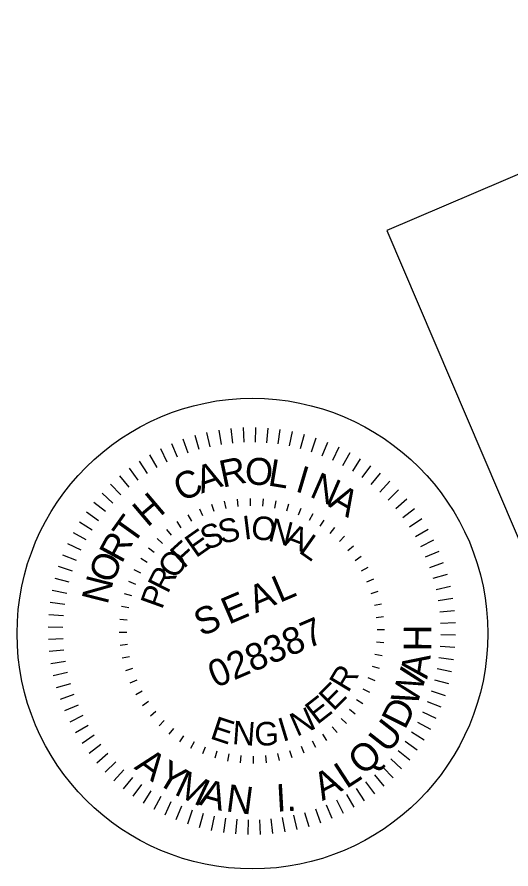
# Model space of a CAD drawing. Extents: x 1882804 to 2194450, y 87424 to 845437.
# Drawn here: x 2194046.1 to 2194137, y 87423.9 to 87580.8 of the extents above; entities that cross this region are included whole.
import ezdxf

# ---------------------------------------------------------------- set-up
doc = ezdxf.new("R2010")
doc.units = 0
doc.layers.add('Scratch_Level_1', color=7, linetype='Continuous')
doc.layers.add('Sheet Title CELL', color=7, linetype='Continuous')

msp = doc.modelspace()

# ---------------------------------------------------------------- linework, layer by layer
at = {"layer": 'Scratch_Level_1'}
msp.add_lwpolyline([(2194158.31, 87438.05), (2194250.33, 87477.33), (2194206.15, 87580.8), (2194114.14, 87541.51)], close=True, dxfattribs=at)
msp.add_circle((2194089.41, 87467.25), 43.34, dxfattribs=at)
msp.add_circle((2194089.41, 87467.25), 43.34, dxfattribs=at)
at = {"layer": 'Sheet Title CELL'}
for p, q in [((2194081.63, 87501.66), (2194081.03, 87504.31)), ((2194083.69, 87502.06), (2194083.26, 87504.74)), ((2194085.77, 87502.34), (2194085.5, 87505.04)), ((2194087.87, 87502.49), (2194087.76, 87505.2)), ((2194089.97, 87502.51), (2194090.02, 87505.22)), ((2194092.07, 87502.41), (2194092.29, 87505.11)), ((2194094.16, 87502.18), (2194094.54, 87504.86)), ((2194096.23, 87501.82), (2194096.77, 87504.48)), ((2194077.59, 87500.49), (2194076.68, 87503.04)), ((2194079.59, 87501.14), (2194078.84, 87503.74)), ((2194098.28, 87501.34), (2194098.98, 87503.96)), ((2194100.29, 87500.74), (2194101.15, 87503.31)), ((2194073.73, 87498.84), (2194072.52, 87501.27)), ((2194075.64, 87499.72), (2194074.57, 87502.22)), ((2194102.26, 87500.01), (2194103.27, 87502.53)), ((2194104.19, 87499.17), (2194105.35, 87501.62)), ((2194071.88, 87497.85), (2194070.52, 87500.19)), ((2194106.06, 87498.21), (2194107.37, 87500.59)), ((2194107.87, 87497.15), (2194109.32, 87499.44)), ((2194070.09, 87496.74), (2194068.6, 87499)), ((2194109.61, 87495.97), (2194111.19, 87498.17)), ((2194066.74, 87494.21), (2194064.98, 87496.28)), ((2194068.38, 87495.53), (2194066.75, 87497.69)), ((2194111.28, 87494.7), (2194112.99, 87496.8)), ((2194065.18, 87492.8), (2194063.3, 87494.76)), ((2194112.87, 87493.32), (2194114.7, 87495.31)), ((2194063.71, 87491.3), (2194061.72, 87493.14)), ((2194114.37, 87491.85), (2194116.32, 87493.73)), ((2194084.56, 87490.28), (2194084.28, 87491.61)), ((2194086.79, 87490.63), (2194086.65, 87491.98)), ((2194089.05, 87490.77), (2194089.03, 87492.13)), ((2194091.31, 87490.69), (2194091.42, 87492.04)), ((2194093.55, 87490.38), (2194093.8, 87491.71)), ((2194115.78, 87490.29), (2194117.84, 87492.05)), ((2194062.33, 87489.71), (2194060.23, 87491.42)), ((2194080.25, 87488.92), (2194079.72, 87490.17)), ((2194082.37, 87489.71), (2194081.96, 87491)), ((2194095.75, 87489.85), (2194096.13, 87491.15)), ((2194097.88, 87489.11), (2194098.39, 87490.37)), ((2194117.09, 87488.65), (2194119.26, 87490.28)), ((2194061.06, 87488.04), (2194058.85, 87489.63)), ((2194078.22, 87487.93), (2194077.57, 87489.12)), ((2194099.94, 87488.17), (2194100.57, 87489.37)), ((2194118.31, 87486.94), (2194120.57, 87488.43)), ((2194059.88, 87486.3), (2194057.59, 87487.75)), ((2194076.29, 87486.75), (2194075.52, 87487.87)), ((2194101.89, 87487.03), (2194102.63, 87488.16)), ((2194058.81, 87484.49), (2194056.44, 87485.8)), ((2194074.49, 87485.38), (2194073.62, 87486.42)), ((2194103.72, 87485.7), (2194104.57, 87486.76)), ((2194119.41, 87485.15), (2194121.76, 87486.5)), ((2194057.86, 87482.62), (2194055.4, 87483.78)), ((2194072.83, 87483.85), (2194071.86, 87484.79)), ((2194105.41, 87484.2), (2194106.36, 87485.17)), ((2194120.41, 87483.3), (2194122.83, 87484.51)), ((2194071.33, 87482.16), (2194070.27, 87483)), ((2194106.95, 87482.54), (2194107.99, 87483.41)), ((2194121.29, 87481.39), (2194123.79, 87482.45)), ((2194057.01, 87480.69), (2194054.5, 87481.71)), ((2194070, 87480.32), (2194068.87, 87481.06)), ((2194108.32, 87480.74), (2194109.44, 87481.5)), ((2194056.29, 87478.72), (2194053.72, 87479.58)), ((2194109.5, 87478.81), (2194110.69, 87479.46)), ((2194122.06, 87479.43), (2194124.61, 87480.35)), ((2194068.86, 87478.37), (2194067.66, 87479)), ((2194122.71, 87477.43), (2194125.31, 87478.19)), ((2194055.69, 87476.71), (2194053.07, 87477.41)), ((2194067.92, 87476.32), (2194066.66, 87476.82)), ((2194110.49, 87476.78), (2194111.74, 87477.31)), ((2194123.23, 87475.4), (2194125.88, 87476)), ((2194055.21, 87474.66), (2194052.55, 87475.2)), ((2194067.18, 87474.18), (2194065.88, 87474.56)), ((2194111.28, 87474.66), (2194112.57, 87475.07)), ((2194054.85, 87472.59), (2194052.16, 87472.97)), ((2194111.85, 87472.47), (2194113.17, 87472.75)), ((2194123.63, 87473.34), (2194126.31, 87473.77)), ((2194066.65, 87471.98), (2194065.32, 87472.23)), ((2194123.91, 87471.25), (2194126.6, 87471.53)), ((2194054.62, 87470.5), (2194051.92, 87470.72)), ((2194066.34, 87469.74), (2194064.99, 87469.86)), ((2194112.2, 87470.24), (2194113.55, 87470.38)), ((2194054.51, 87468.4), (2194051.8, 87468.46)), ((2194124.06, 87469.16), (2194126.77, 87469.27)), ((2194066.26, 87467.48), (2194064.9, 87467.46)), ((2194112.34, 87467.98), (2194113.69, 87467.99)), ((2194124.08, 87467.06), (2194126.79, 87467)), ((2194054.54, 87466.3), (2194051.83, 87466.19)), ((2194066.39, 87465.22), (2194065.04, 87465.07)), ((2194112.25, 87465.72), (2194113.6, 87465.6)), ((2194123.98, 87464.96), (2194126.68, 87464.74)), ((2194054.69, 87464.21), (2194051.99, 87463.93)), ((2194111.94, 87463.48), (2194113.28, 87463.23)), ((2194054.96, 87462.13), (2194052.29, 87461.69)), ((2194066.75, 87462.99), (2194065.42, 87462.71)), ((2194123.75, 87462.87), (2194126.43, 87462.49)), ((2194067.32, 87460.8), (2194066.03, 87460.4)), ((2194111.42, 87461.28), (2194112.72, 87460.9)), ((2194123.39, 87460.8), (2194126.05, 87460.26)), ((2194055.36, 87460.06), (2194052.72, 87459.46)), ((2194068.11, 87458.68), (2194066.86, 87458.15)), ((2194110.68, 87459.14), (2194111.94, 87458.64)), ((2194122.91, 87458.75), (2194125.53, 87458.05)), ((2194055.89, 87458.03), (2194053.29, 87457.27)), ((2194109.74, 87457.09), (2194110.94, 87456.46)), ((2194056.54, 87456.02), (2194053.98, 87455.11)), ((2194069.09, 87456.65), (2194067.91, 87456)), ((2194122.3, 87456.74), (2194124.88, 87455.88)), ((2194057.3, 87454.07), (2194054.81, 87453)), ((2194070.28, 87454.72), (2194069.16, 87453.96)), ((2194108.59, 87455.14), (2194109.73, 87454.4)), ((2194121.58, 87454.77), (2194124.1, 87453.75)), ((2194071.65, 87452.92), (2194070.61, 87452.05)), ((2194107.27, 87453.31), (2194108.32, 87452.46)), ((2194120.74, 87452.84), (2194123.19, 87451.68)), ((2194058.19, 87452.16), (2194055.76, 87450.95)), ((2194073.18, 87451.26), (2194072.23, 87450.29)), ((2194105.77, 87451.61), (2194106.74, 87450.67)), ((2194119.78, 87450.97), (2194122.16, 87449.66)), ((2194059.18, 87450.31), (2194056.84, 87448.95)), ((2194074.87, 87449.76), (2194074.02, 87448.7)), ((2194104.11, 87450.08), (2194104.98, 87449.04)), ((2194060.29, 87448.53), (2194058.03, 87447.03)), ((2194076.7, 87448.43), (2194075.96, 87447.3)), ((2194102.31, 87448.71), (2194103.07, 87447.59)), ((2194118.71, 87449.16), (2194121.01, 87447.71)), ((2194061.5, 87446.81), (2194059.33, 87445.18)), ((2194078.66, 87447.29), (2194078.03, 87446.09)), ((2194080.71, 87446.35), (2194080.21, 87445.09)), ((2194098.35, 87446.54), (2194098.88, 87445.29)), ((2194100.38, 87447.53), (2194101.03, 87446.34)), ((2194117.54, 87447.42), (2194119.74, 87445.83)), ((2194062.81, 87445.17), (2194060.75, 87443.41)), ((2194082.85, 87445.61), (2194082.47, 87444.31)), ((2194085.05, 87445.08), (2194084.8, 87443.75)), ((2194087.29, 87444.78), (2194087.17, 87443.43)), ((2194089.55, 87444.69), (2194089.56, 87443.33)), ((2194091.81, 87444.82), (2194091.95, 87443.48)), ((2194094.04, 87445.18), (2194094.32, 87443.85)), ((2194096.22, 87445.75), (2194096.63, 87444.46)), ((2194116.26, 87445.75), (2194118.36, 87444.03)), ((2194064.23, 87443.61), (2194062.27, 87441.73)), ((2194114.89, 87444.16), (2194116.88, 87442.32)), ((2194065.73, 87442.14), (2194063.89, 87440.15)), ((2194113.41, 87442.66), (2194115.3, 87440.7)), ((2194067.32, 87440.76), (2194065.6, 87438.66)), ((2194110.22, 87439.93), (2194111.85, 87437.77)), ((2194111.86, 87441.25), (2194113.62, 87439.18)), ((2194068.98, 87439.49), (2194067.4, 87437.29)), ((2194070.73, 87438.31), (2194069.28, 87436.02)), ((2194108.5, 87438.72), (2194110, 87436.46)), ((2194072.54, 87437.24), (2194071.23, 87434.87)), ((2194106.71, 87437.62), (2194108.07, 87435.27)), ((2194074.41, 87436.29), (2194073.25, 87433.84)), ((2194076.33, 87435.45), (2194075.32, 87432.93)), ((2194102.96, 87435.74), (2194104.02, 87433.24)), ((2194104.87, 87436.62), (2194106.08, 87434.19)), ((2194078.31, 87434.72), (2194077.45, 87432.15)), ((2194080.32, 87434.12), (2194079.62, 87431.5)), ((2194082.37, 87433.64), (2194081.82, 87430.98)), ((2194096.97, 87433.8), (2194097.56, 87431.15)), ((2194099, 87434.32), (2194099.76, 87431.72)), ((2194101, 87434.97), (2194101.91, 87432.42)), ((2194084.44, 87433.28), (2194084.06, 87430.6)), ((2194086.53, 87433.05), (2194086.31, 87430.35)), ((2194088.62, 87432.95), (2194088.57, 87430.24)), ((2194090.73, 87432.97), (2194090.84, 87430.26)), ((2194092.82, 87433.12), (2194093.1, 87430.42)), ((2194094.91, 87433.39), (2194095.34, 87430.72))]:
    msp.add_line(p, q, dxfattribs=at)

# ---------------------------------------------------------------- texts
for s, height, rotation, p in [('R', 4.97, 11.906, (2194083.92, 87494.11)), ('O', 4.97, 357.7276, (2194087.95, 87494.73)), ('A', 4.97, 18.9953, (2194080.01, 87493.01)), ('L', 4.97, 350.6383, (2194092.11, 87494.56)), ('I', 4.97, 343.5491, (2194097.1, 87493.5)), ('C', 4.97, 26.0845, (2194076.41, 87491.4)), ('N', 4.97, 336.4599, (2194099.74, 87492.55)), ('H', 4.97, 40.2629, (2194070.05, 87486.71)), ('A', 4.97, 329.3706, (2194103.25, 87490.76)), ('T', 4.97, 54.4414, (2194067.37, 87483.36)), ('S', 4.34, 13.9899, (2194083.7, 87483.71)), ('I', 4.34, 6.9578, (2194087.88, 87484.54)), ('O', 4.34, 352.8935, (2194088.98, 87484.76)), ('N', 4.34, 345.8614, (2194092.11, 87484.4)), ('S', 4.34, 21.022, (2194080.84, 87482.54)), ('A', 4.34, 338.8293, (2194095.02, 87483.59)), ('R', 4.97, 61.5306, (2194065.32, 87480)), ('E', 4.34, 35.0863, (2194078.99, 87481.09)), ('L', 4.34, 324.7651, (2194097.74, 87482.29)), ('F', 4.34, 42.1184, (2194076.74, 87479.1)), ('O', 4.34, 56.1826, (2194075.28, 87477.09)), ('O', 4.97, 68.6199, (2194063.72, 87476.26)), ('R', 4.34, 63.2147, (2194073.81, 87474.45)), ('N', 4.97, 75.7091, (2194062.71, 87472.45)), ('L', 4.97, 23.1205, (2194094.41, 87472.87)), ('P', 4.34, 70.2469, (2194072.76, 87471.55)), ('A', 4.97, 23.1205, (2194089.99, 87470.96)), ('E', 4.97, 23.1205, (2194085.03, 87468.86)), ('S', 4.97, 23.1205, (2194079.98, 87466.66)), ('028387', 4.97, 23.1205, (2194082.6, 87457.17)), ('H', 5.05, 89.7444, (2194122.31, 87463.99)), ('A', 5.05, 81.3518, (2194121.58, 87458.79)), ('R', 4.34, 59.0178, (2194107.02, 87456.21)), ('W', 5.05, 71.9019, (2194119.59, 87453.66)), ('E', 4.34, 44.9535, (2194104.29, 87452.85)), ('E', 4.34, 37.9214, (2194101.32, 87450.37)), ('D', 5.05, 63.5093, (2194117.48, 87449.41)), ('N', 4.34, 23.8572, (2194097.55, 87448.21)), ('E', 4.34, 341.6644, (2194081.42, 87447.99)), ('N', 4.34, 355.7287, (2194085.59, 87446.9)), ('G', 4.34, 2.7608, (2194089.86, 87446.54)), ('I', 4.34, 16.825, (2194094.95, 87447.3)), ('U', 5.05, 51.8886, (2194114.39, 87445.02)), ('Q', 5.05, 41.59, (2194109.79, 87440.93)), ('A', 5.05, 323.4723, (2194067.49, 87442.48)), ('Y', 5.05, 328.9165, (2194071.38, 87439.87)), ('L', 5.05, 33.0598, (2194106.69, 87438.57)), ('M', 5.05, 334.963, (2194074.82, 87437.71)), ('A', 5.05, 27.5337, (2194102.29, 87436.39)), ('A', 5.05, 344.3848, (2194079.41, 87435.78)), ('N', 5.05, 352.5433, (2194084.37, 87434.54)), ('I.', 5.048, 3.2047, (2194093.87, 87434.44))]:
    msp.add_text(s, height=height, rotation=rotation, dxfattribs=at).set_placement(p)

doc.saveas('drawing.dxf')
